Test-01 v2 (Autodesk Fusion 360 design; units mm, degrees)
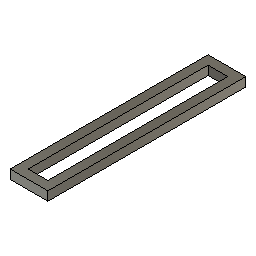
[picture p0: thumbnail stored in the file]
sketch "Sketch1" plane through (0, 0, 0) normal (0, 0, 1) x axis (1, 0, 0)
  line L1 (-11, 0) -> (0, 0)
  line L2 (-11, 100) -> (-11, 0)
  line L3 (0, 100) -> (-11, 100)
  line L4 (0, 0) -> (0, 100)
  line L5 (-16, -5) -> (5, -5)
  line L6 (-16, 105) -> (-16, -5)
  line L7 (5, 105) -> (-16, 105)
  line L8 (5, -5) -> (5, 105)
  point P1 (0, 0)
  point P2 (0, 0)
  point P3 (-11, 0)
  point P5 (0, 100)
  point P6 (5, -5)
  point P9 (5, 105)
  point P4 (-11, 100)
  point P8 (-16, 105)
  horizontal L1
  vertical L2
  horizontal L3
  vertical L4
  coincident P1 P2
  horizontal L5
  vertical L6
  horizontal L7
  vertical L8
  dimension "d1" distance P2 P3 = 11
  dimension "d2" distance P2 P5 = 100
  dimension "d6" distance P1 P6 = 5
  dimension "d8" distance P5 P9 = 5
  dimension "d9" distance P4 P8 = 5
  dimension "d10" distance P5 P9 = 5
extrude "Extrude1" new body sketch "Sketch1" along normal blind 5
